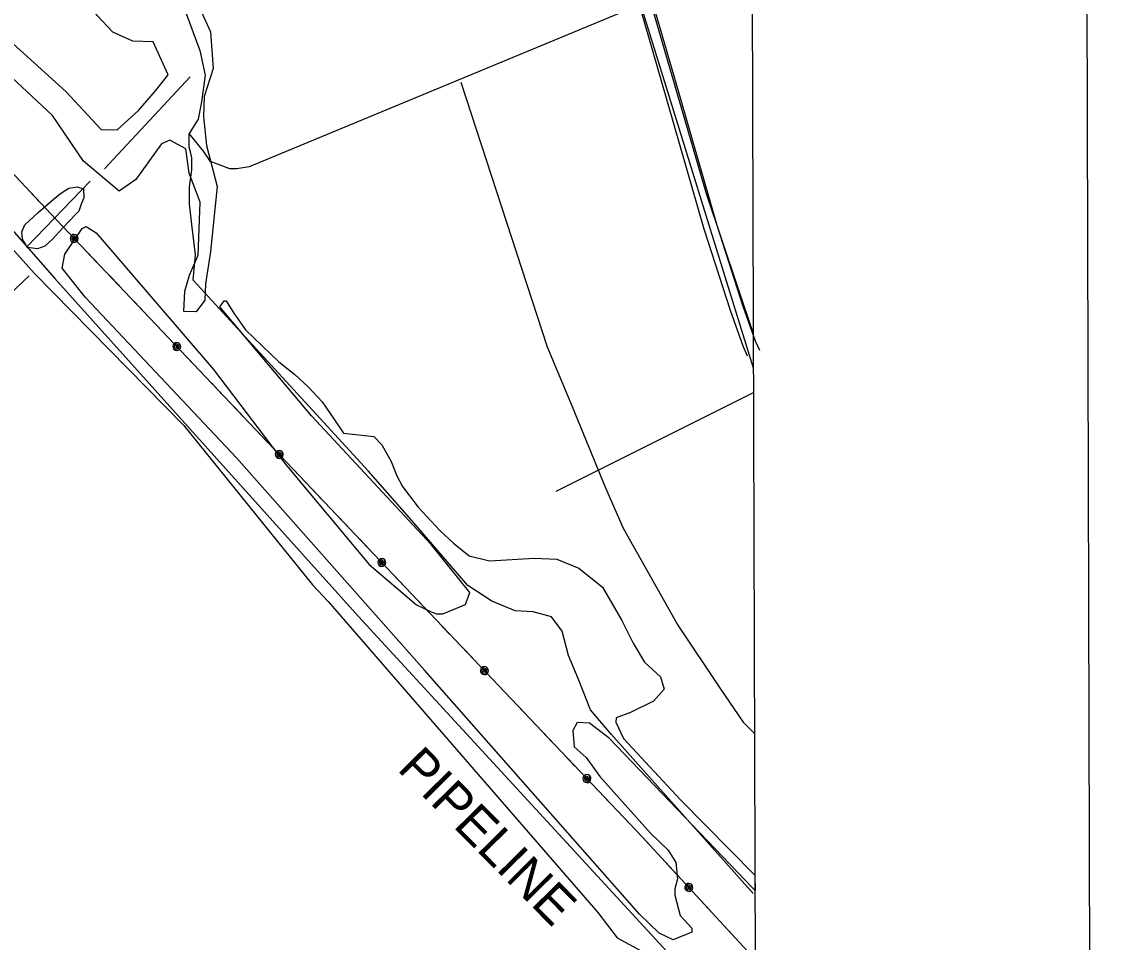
# Model space of a CAD drawing. Extents: x 3355677 to 3393573, y 612928 to 638357.
# Drawn here: x 3389732 to 3392155, y 625128 to 627193 of the extents above; entities that cross this region are included whole.
import ezdxf

# ---------------------------------------------------------------- set-up
doc = ezdxf.new("R2010")
doc.units = 0
for name, color, linetype in [('V-ANNO-SYMB', 7, 'Continuous'), ('V-GRID-FRAM', 7, 'Continuous'), ('V-ROAD-CNTR', 7, 'Continuous'), ('V-SITE-VEGE', 7, 'Continuous'), ('V-TOPO-SHOR', 7, 'Continuous'), ('V-UTIL-IDEN', 7, 'Continuous'), ('V-UTIL-LINE', 7, 'Continuous')]:
    doc.layers.add(name, color=color, linetype=linetype)

msp = doc.modelspace()

# ---------------------------------------------------------------- linework, layer by layer
at = {"layer": 'V-ANNO-SYMB'}
msp.add_lwpolyline([(3359071.7, 614143.5), (3392154.8, 614230.1), (3392094.8, 637146.6), (3359011.7, 637060), (3359071.7, 614143.5)], dxfattribs=at)
at = {"layer": 'V-GRID-FRAM'}
msp.add_lwpolyline([(3359767.9, 636495.9), (3391341.6, 636578.5), (3391397.2, 618394.8), (3359807.6, 618312.1), (3359767.9, 636495.9)], dxfattribs=at)
at = {"layer": 'V-ROAD-CNTR'}
for points in [[(3390687.5, 628818.2), (3390723.3, 628697.7), (3390813, 628401.7), (3390924, 628001.3), (3391091.4, 627426.8), (3391195.4, 627066.5), (3391290.5, 626737.1), (3391348.6, 626555.4), (3391376.8, 626477.1), (3391386.2, 626456.2)], [(3390818.8, 628268.3), (3390895.1, 627993.1), (3391062.6, 627418.4), (3391166.6, 627058.2), (3391261.8, 626728.4), (3391320.2, 626545.8), (3391348.9, 626465.9), (3391358.9, 626443.8)]]:
    msp.add_lwpolyline(points, dxfattribs=at)
at = {"layer": 'V-SITE-VEGE'}
for p, q in [((3389454.2, 626968.4), (3389761.3, 626628.6)), ((3389829.1, 626671.7), (3389867.8, 626729.6)), ((3389867.8, 626729.6), (3389877.1, 626733.8)), ((3389877.1, 626733.8), (3389899.4, 626719.3)), ((3389899.4, 626719.3), (3390162.1, 626413)), ((3389823.4, 626640), (3389829.1, 626671.7)), ((3389761.3, 626628.6), (3390095.8, 626287.7)), ((3389875.8, 626574.2), (3389823.4, 626640)), ((3390214.1, 626214.9), (3389875.8, 626574.2)), ((3390176.4, 626554), (3390186, 626567.3)), ((3390382, 626309.1), (3390176.4, 626554)), ((3390186, 626567.3), (3390190.6, 626567.1)), ((3390190.6, 626567.1), (3390207.8, 626539.1)), ((3390207.8, 626539.1), (3390233.8, 626501.7)), ((3390233.8, 626501.7), (3390308.9, 626430.5)), ((3390162.1, 626413), (3390323.3, 626201.8)), ((3390308.9, 626430.5), (3390344.3, 626401.8)), ((3390344.3, 626401.8), (3390375.2, 626373.2)), ((3390375.2, 626373.2), (3390406, 626340.2)), ((3390406, 626340.2), (3390432, 626302.7)), ((3390095.8, 626287.7), (3390384, 625930.3)), ((3390649.9, 626020.9), (3390382, 626309.1)), ((3390432, 626302.7), (3390453.6, 626270)), ((3390453.6, 626270), (3390521.9, 626262.9)), ((3390521.9, 626262.9), (3390539.4, 626244)), ((3390539.4, 626244), (3390560.9, 626206.7)), ((3390635, 625738.6), (3390214.1, 626214.9)), ((3390323.3, 626201.8), (3390511.3, 625975.8)), ((3390560.9, 626206.7), (3390573.4, 626174.3)), ((3390573.4, 626174.3), (3390586.2, 626151)), ((3390586.2, 626151), (3390621.1, 626104.1)), ((3390621.1, 626104.1), (3390669.4, 626052.1)), ((3390669.4, 626052.1), (3390700.3, 626023.6)), ((3390737.3, 625912.8), (3390649.9, 626020.9)), ((3390700.3, 626023.6), (3390735.8, 625994.9)), ((3390511.3, 625975.8), (3390617.5, 625885.2)), ((3390735.8, 625994.9), (3390781, 625984.1)), ((3390781, 625984.1), (3390881.7, 625989.6)), ((3390881.7, 625989.6), (3390931.9, 625987.7)), ((3390931.9, 625987.7), (3390981.3, 625967.6)), ((3390981.3, 625967.6), (3391034.6, 625924.6)), ((3390384, 625930.3), (3390419.2, 625892.5)), ((3391034.6, 625924.6), (3391077.5, 625850)), ((3390727.2, 625885.8), (3390737.3, 625912.8)), ((3390419.2, 625892.5), (3391023.6, 625195)), ((3390617.5, 625885.2), (3390649, 625870.4)), ((3390676.2, 625864.8), (3390727.2, 625885.8)), ((3390649, 625870.4), (3390662.5, 625865.3)), ((3390662.5, 625865.3), (3390676.2, 625864.8)), ((3391077.5, 625850), (3391103, 625798.9)), ((3391103, 625798.9), (3391128.8, 625756.9)), ((3391128.8, 625756.9), (3391164.1, 625723.6)), ((3391117.1, 625191.5), (3390635, 625738.6)), ((3391164.1, 625723.6), (3391172.3, 625696)), ((3391172.3, 625696), (3391148.5, 625669.5)), ((3391148.5, 625669.5), (3391097.3, 625644)), ((3391097.3, 625644), (3391064.9, 625631.5)), ((3390977.7, 625621), (3390967.9, 625603.1)), ((3391005.1, 625620), (3390977.7, 625621)), ((3391049.5, 625586.4), (3391005.1, 625620)), ((3391064.9, 625631.5), (3391064.5, 625622.4)), ((3391064.5, 625622.4), (3391081.4, 625585.2)), ((3390967.9, 625603.1), (3390971.1, 625566.5)), ((3391370.5, 625250.6), (3391049.5, 625586.4)), ((3391081.4, 625585.2), (3391208.8, 625448.2)), ((3390971.1, 625566.5), (3390997.6, 625542.7)), ((3390997.6, 625542.7), (3391028.1, 625500.5)), ((3391028.1, 625500.5), (3391142.1, 625373.1)), ((3391208.8, 625448.2), (3391376.1, 625279)), ((3391142.1, 625373.1), (3391181.8, 625335.2)), ((3391181.8, 625335.2), (3391199, 625307.1)), ((3391199, 625307.1), (3391202.2, 625270.5)), ((3391202.2, 625270.5), (3391196.8, 625247.9)), ((3391376.1, 625279), (3391376.2, 625244.4)), ((3391196.8, 625247.9), (3391196.3, 625234.2)), ((3391376.2, 625244.4), (3391370.5, 625250.6)), ((3391196.3, 625234.2), (3391208.3, 625188.2)), ((3391023.6, 625195), (3391067.2, 625138.6)), ((3391161.2, 625148.8), (3391117.1, 625191.5)), ((3391208.3, 625188.2), (3391234.7, 625159.8)), ((3391192.6, 625134), (3391161.2, 625148.8)), ((3391234.4, 625150.7), (3391192.6, 625134)), ((3391234.7, 625159.8), (3391234.4, 625150.7)), ((3391067.2, 625138.6), (3391120.9, 625109.3))]:
    msp.add_line(p, q, dxfattribs=at)
for points in [[(3389944.5, 627881.1), (3390014.8, 627805.5), (3390022.9, 627777.9), (3390019.5, 627686.7), (3389981.7, 627651.6), (3389978.3, 627560.5), (3389995.6, 627532.5), (3390040.2, 627503.5), (3390046.9, 627439.3), (3390045.6, 627402.9), (3390062.8, 627374.9), (3390155.8, 627170.7), (3390161.9, 627088.3), (3390141.3, 627025.2), (3390139.6, 626979.7), (3390146.4, 626915.5), (3390170.4, 626823.4), (3390155.9, 626677.9), (3390144.1, 626605.3), (3390142.7, 626568.9), (3390123.5, 626542.2), (3390096.1, 626543.2), (3390097.8, 626588.8)], [(3389610.2, 627236.4), (3389831.2, 627036.7), (3389910.2, 626951.6), (3389946.7, 626950.3), (3389994, 626994.1), (3390032.2, 627038.4), (3390060.9, 627073.8), (3390027.1, 627148.1), (3389981.5, 627149.7), (3389936.5, 627169.6), (3389901.4, 627207.4), (3389875.4, 627244.9), (3389849.7, 627291.5), (3389805.4, 627329.6), (3389770, 627358.3), (3389698.7, 627406.6)], [(3390097.8, 626588.8), (3390108.2, 626624.9), (3390128.2, 626669.8), (3390132.5, 626788.3), (3390107.5, 626853.1), (3390100.4, 626908.1), (3390064.6, 626927.7), (3390046, 626919.2), (3389988.3, 626839.2), (3389950.8, 626813.2), (3389871.1, 626880), (3389801.8, 626983), (3389607.5, 627163.5)]]:
    msp.add_lwpolyline(points, dxfattribs=at)
msp.add_lwpolyline([(3389854.4, 626762.2), (3389824.7, 626730.7), (3389801.4, 626705.1), (3389784.5, 626689.5), (3389768, 626684), (3389745.7, 626686.8), (3389734.2, 626705.6), (3389732.8, 626721.9), (3389739.5, 626737.9), (3389769, 626765.3), (3389802.6, 626794.6), (3389819.4, 626808.2), (3389838.2, 626819.7), (3389856.6, 626823.1), (3389870.7, 626818.5), (3389872, 626798.1), (3389865.4, 626784.1), (3389860.7, 626768)], close=True, dxfattribs=at)
at = {"layer": 'V-TOPO-SHOR'}
for p, q in [((3390110.4, 627069.6), (3389918.2, 626862.8)), ((3389745, 626688.6), (3389885.7, 626835.6)), ((3390930.4, 626140), (3391372.8, 626361.2))]:
    msp.add_line(p, q, dxfattribs=at)
for points in [[(3390910.6, 628033.7), (3391266.4, 626808.1), (3391372.4, 626493.8)], [(3390886.9, 628017.9), (3390720.9, 627855.8), (3390630, 627756.9), (3390491.6, 627642.3), (3390290, 627432.8), (3390195.1, 627330), (3390171.4, 627290.4), (3390151.6, 627250.9), (3390096.3, 627223.2), (3390131.8, 627128.4), (3390143.7, 627073), (3390135.8, 627013.7), (3390127.9, 626974.2), (3390108.1, 626942.6)], [(3391372.7, 626416.3), (3391124.1, 627219.3), (3391100.4, 627223.2), (3390242.5, 626867.4), (3390214.9, 626863.5), (3390199, 626863.5), (3390155.6, 626879.3), (3390139.7, 626903), (3390108.1, 626942.6)], [(3390716.9, 627057.2), (3390910.6, 626464.2), (3390966, 626329.8), (3391041.1, 626147.9), (3391080.6, 626057), (3391203.2, 625839.6), (3391298.1, 625697.3), (3391349.5, 625622.1), (3391375.2, 625596.4)], [(3391371.9, 625238), (3391053.4, 625595.5), (3391007.1, 625649.6), (3390979.8, 625720.1), (3390958, 625771.7), (3390944.2, 625825.9), (3390919.7, 625858.4), (3390879, 625869.2), (3390838.3, 625871.8), (3390786.6, 625893.4), (3390732.3, 625928.5), (3390607, 626074.7), (3390509, 626185.8), (3390117, 626613.6), (3390122.3, 626670.6), (3390114, 626738.4), (3390108.4, 626784.6), (3390108.4, 626822.6), (3390113.7, 626860.6), (3390113.6, 626887.7), (3390110.9, 626901.3), (3390108.1, 626912.1), (3390108.1, 626942.6)], [(3387513.3, 624469.5), (3388491.2, 625432.5), (3389749, 626623.2)]]:
    msp.add_lwpolyline(points, dxfattribs=at)
at = {"layer": 'V-UTIL-LINE'}
for points in [[(3385622.4, 630705.4), (3386548, 629954.5), (3387768, 628752.6), (3389034.8, 627575.9), (3389809.8, 626749.6), (3391123.1, 625365), (3391367.6, 625099.5)], [(3387729.7, 628621.6), (3389263.6, 627200.3), (3389619.3, 626830.2), (3389806.8, 626616.9), (3390487.3, 625858.9), (3391377.3, 624891.7)], [(3389749.3, 626814.1), (3389772.6, 626789.3)], [(3389799.9, 626760.1), (3389809.8, 626749.6), (3389823.3, 626735.4)], [(3389850.1, 626707.1), (3389850.7, 626709.9), (3389848.6, 626709), (3389848.1, 626706.3), (3389850.3, 626704.4), (3389852.9, 626706.6), (3389853.1, 626711.3), (3389849.1, 626712.9), (3389844.9, 626710.6), (3389844.5, 626706), (3389846.8, 626702.2), (3389851.6, 626701.6), (3389855.8, 626705.1), (3389856.6, 626713.3), (3389853.8, 626715.3), (3389850.3, 626716.1), (3389846.9, 626715.5), (3389843.9, 626713.6), (3389841.9, 626710.7), (3389841.1, 626707.3), (3389841.7, 626703.8), (3389843.6, 626700.9), (3389846.4, 626698.8), (3389849.9, 626698.1), (3389853.3, 626698.7), (3389856.3, 626700.5), (3389858.3, 626703.4), (3389859.1, 626706.8), (3389858.5, 626710.3), (3389856.6, 626713.3)], [(3389876.9, 626678.8), (3389900.3, 626654.1)], [(3389927.9, 626625.1), (3389951.3, 626600.4)], [(3389978.8, 626571.4), (3390002.2, 626546.7)], [(3390029.7, 626517.7), (3390053.1, 626493)], [(3390080, 626464.7), (3390080.5, 626467.5), (3390078.4, 626466.6), (3390077.9, 626463.9), (3390080.1, 626462), (3390082.7, 626464.3), (3390083, 626468.9), (3390079, 626470.5), (3390074.7, 626468.2), (3390074.4, 626463.7), (3390076.7, 626459.8), (3390081.4, 626459.3), (3390085.7, 626462.8), (3390086.5, 626470.9), (3390083.6, 626473), (3390080.2, 626473.7), (3390076.7, 626473.1), (3390073.8, 626471.3), (3390071.7, 626468.4), (3390071, 626465), (3390071.6, 626461.5), (3390073.4, 626458.5), (3390076.3, 626456.5), (3390079.7, 626455.7), (3390083.2, 626456.3), (3390086.1, 626458.2), (3390088.2, 626461.1), (3390089, 626464.5), (3390088.4, 626468), (3390086.5, 626470.9)], [(3390106.8, 626436.4), (3390130.2, 626411.8)], [(3390157.7, 626382.8), (3390181.1, 626358.1)], [(3390208.6, 626329.1), (3390232, 626304.4)], [(3390259.6, 626275.4), (3390283, 626250.7)], [(3390309.8, 626222.4), (3390310.4, 626225.2), (3390308.3, 626224.3), (3390307.8, 626221.6), (3390310, 626219.7), (3390312.6, 626221.9), (3390312.8, 626226.6), (3390308.9, 626228.2), (3390304.6, 626225.9), (3390304.2, 626221.4), (3390306.5, 626217.5), (3390311.3, 626216.9), (3390315.5, 626220.5), (3390316.3, 626228.6), (3390313.5, 626230.6), (3390310, 626231.4), (3390306.6, 626230.8), (3390303.6, 626228.9), (3390301.6, 626226.1), (3390300.8, 626222.6), (3390301.4, 626219.2), (3390303.3, 626216.2), (3390306.1, 626214.2), (3390309.6, 626213.4), (3390313, 626214), (3390316, 626215.9), (3390318, 626218.7), (3390318.8, 626222.2), (3390318.2, 626225.6), (3390316.3, 626228.6)], [(3390336.6, 626194.1), (3390360, 626169.4)], [(3390387.6, 626140.4), (3390411, 626115.8)], [(3390438.5, 626086.7), (3390461.9, 626062.1)], [(3390489.4, 626033.1), (3390512.8, 626008.4)], [(3390539.7, 625980.1), (3390540.3, 625982.9), (3390538.1, 625982), (3390537.6, 625979.3), (3390539.9, 625977.4), (3390542.4, 625979.6), (3390542.7, 625984.3), (3390538.7, 625985.9), (3390534.4, 625983.6), (3390534.1, 625979), (3390536.4, 625975.2), (3390541.2, 625974.6), (3390545.4, 625978.2), (3390546.2, 625986.3), (3390543.3, 625988.3), (3390539.9, 625989.1), (3390536.4, 625988.5), (3390533.5, 625986.6), (3390531.4, 625983.7), (3390530.7, 625980.3), (3390531.3, 625976.9), (3390533.1, 625973.9), (3390536, 625971.9), (3390539.4, 625971.1), (3390542.9, 625971.7), (3390545.9, 625973.5), (3390547.9, 625976.4), (3390548.7, 625979.8), (3390548.1, 625983.3), (3390546.2, 625986.3)], [(3390566.5, 625951.8), (3390589.9, 625927.1)], [(3390617.4, 625898.1), (3390640.8, 625873.4)], [(3390668.3, 625844.4), (3390691.7, 625819.7)], [(3390719.3, 625790.7), (3390742.7, 625766.1)], [(3390769.5, 625737.8), (3390770.1, 625740.6), (3390768, 625739.7), (3390767.5, 625737), (3390769.7, 625735.1), (3390772.3, 625737.3), (3390772.5, 625742), (3390768.6, 625743.6), (3390764.3, 625741.3), (3390763.9, 625736.7), (3390766.2, 625732.9), (3390771, 625732.3), (3390775.2, 625735.8), (3390776, 625743.9), (3390773.2, 625746), (3390769.8, 625746.7), (3390766.3, 625746.2), (3390763.3, 625744.3), (3390761.3, 625741.4), (3390760.5, 625738), (3390761.1, 625734.5), (3390763, 625731.6), (3390765.9, 625729.5), (3390769.3, 625728.8), (3390772.7, 625729.3), (3390775.7, 625731.2), (3390777.7, 625734.1), (3390778.5, 625737.5), (3390777.9, 625741), (3390776, 625743.9)], [(3390796.3, 625709.5), (3390819.7, 625684.8)], [(3390847.3, 625655.8), (3390870.7, 625631.1)], [(3390898.2, 625602.1), (3390921.6, 625577.4)], [(3390949.1, 625548.4), (3390972.5, 625523.7)], [(3390999.4, 625495.4), (3391000, 625498.2), (3390997.8, 625497.3), (3390997.3, 625494.6), (3390999.6, 625492.7), (3391002.1, 625495), (3391002.4, 625499.6), (3390998.4, 625501.2), (3390994.1, 625498.9), (3390993.8, 625494.4), (3390996.1, 625490.5), (3391000.9, 625490), (3391005.1, 625493.5), (3391005.9, 625501.6), (3391003, 625503.6), (3390999.6, 625504.4), (3390996.1, 625503.8), (3390993.2, 625502), (3390991.1, 625499.1), (3390990.4, 625495.7), (3390991, 625492.2), (3390992.8, 625489.2), (3390995.7, 625487.2), (3390999.1, 625486.4), (3391002.6, 625487), (3391005.6, 625488.9), (3391007.6, 625491.8), (3391008.4, 625495.2), (3391007.8, 625498.6), (3391005.9, 625501.6)], [(3391026.2, 625467.1), (3391049.6, 625442.5)], [(3391077.1, 625413.4), (3391100.5, 625388.8)], [(3391128, 625359.7), (3391151, 625334.7)], [(3391178.1, 625305.3), (3391201.1, 625280.2)], [(3391227.6, 625251.5), (3391228.2, 625254.3), (3391226, 625253.5), (3391225.5, 625250.8), (3391227.7, 625248.9), (3391230.3, 625251), (3391230.6, 625255.7), (3391226.7, 625257.4), (3391222.4, 625255.1), (3391222, 625250.6), (3391224.2, 625246.7), (3391229, 625246.1), (3391233.2, 625249.5), (3391234.2, 625257.6), (3391231.3, 625259.7), (3391227.9, 625260.5), (3391224.5, 625260), (3391221.5, 625258.2), (3391219.4, 625255.3), (3391218.6, 625251.9), (3391219.1, 625248.4), (3391220.9, 625245.4), (3391223.8, 625243.4), (3391227.2, 625242.6), (3391230.7, 625243.1), (3391233.7, 625244.9), (3391235.7, 625247.8), (3391236.6, 625251.2), (3391236, 625254.6), (3391234.2, 625257.6)], [(3391254, 625222.9), (3391277, 625197.9)], [(3391304.1, 625168.4), (3391327.1, 625143.4)]]:
    msp.add_lwpolyline(points, dxfattribs=at)

# ---------------------------------------------------------------- texts
at = {"layer": 'V-UTIL-IDEN'}
msp.add_text('PIPELINE', height=83, rotation=314.6895, dxfattribs=at).set_placement((3390572, 625515.3))

doc.saveas('drawing.dxf')
